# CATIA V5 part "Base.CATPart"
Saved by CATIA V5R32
Part number: Base
Bounding box of the stored display mesh (mm): x -23.876 to 23.876, y 0 to 88.9, z 0 to 54.102
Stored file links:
  D:\PROJECTS\Project 2022\CATIA V5 6R 2022\Resources\Part Files\c13_catia_v5_6r2022_prt\c13_catia_v5-6r2022_figr_13-45\Part & Asm files\Base.CATPart
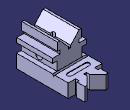
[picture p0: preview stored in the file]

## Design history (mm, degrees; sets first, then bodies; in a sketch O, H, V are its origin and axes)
Body1 (main body)
  Sketch1 on xy-plane, origin (0, 0, 0), H (1, 0, 0), V (0, 1, 0)
    line L1 (-23.876, 0) -> (23.876, 0)
    point P1 (-23.876, 0)
    point P2 (23.876, 0)
    construction line L2 (-23.876, 50.8) -> (23.876, 50.8)
    point P3 (-23.876, 50.8)
    point P4 (23.876, 50.8)
    line L3 (23.876, 0) -> (23.876, 72.898)
    point P5 (23.876, 72.898)
    line L4 (23.876, 72.898) -> (13.462, 72.898)
    point P6 (13.462, 72.898)
    line L5 (13.462, 72.898) -> (13.462, 77.724)
    point P7 (13.462, 77.724)
    line L6 (13.462, 77.724) -> (16.51, 77.724)
    point P8 (16.51, 77.724)
    line L7 (16.51, 77.724) -> (16.51, 88.9)
    point P9 (16.51, 88.9)
    line L8 (16.51, 88.9) -> (13.462, 88.9)
    point P10 (13.462, 88.9)
    line L9 (13.462, 88.9) -> (1.778, 77.724)
    point P11 (1.778, 77.724)
    line L10 (1.778, 77.724) -> (1.778, 72.898)
    point P12 (1.778, 72.898)
    line L11 (1.778, 72.898) -> (0, 72.898)
    point P13 (0, 72.898)
    point P14 (0, 72.898)
    point P15 (-1.778, 72.898)
    line L12 (-1.778, 72.898) -> (0, 72.898)
    point P16 (-1.778, 77.724)
    line L13 (-1.778, 77.724) -> (-1.778, 72.898)
    point P17 (-13.462, 88.9)
    line L14 (-13.462, 88.9) -> (-1.778, 77.724)
    point P18 (-16.51, 88.9)
    line L15 (-16.51, 88.9) -> (-13.462, 88.9)
    point P19 (-16.51, 77.724)
    line L16 (-16.51, 77.724) -> (-16.51, 88.9)
    point P20 (-13.462, 77.724)
    line L17 (-13.462, 77.724) -> (-16.51, 77.724)
    point P21 (-13.462, 72.898)
    line L18 (-13.462, 72.898) -> (-13.462, 77.724)
    point P22 (-23.876, 72.898)
    line L19 (-23.876, 72.898) -> (-13.462, 72.898)
    point P23 (-23.876, 50.8)
    point P24 (23.876, 50.8)
    construction line L20 (23.876, 50.8) -> (-23.876, 50.8)
    point P25 (-23.876, 0)
    line L21 (-23.876, 0) -> (-23.876, 72.898)
    length L1 = 47.752
    distance P2 V = 23.876
    distance L2 L1 = 50.8
    distance P5 L2 = 22.098
    distance L7 P1 = 40.386
    distance L5 P1 = 37.338
    distance L2 P7 = 26.924
    distance P9 L2 = 38.1
    distance P10 L3 = 10.414
    distance L10 L3 = 22.098
    distance L11 L2 = 22.098
    distance P11 L2 = 26.924
    horizontal: L1 H, L2 H, L4 H, L6 H, L8 H, L11 H
    coincidence: H L1, P13 V, P13 P14
    vertical: L3 V, L5 V, L7 V, L10 V
    symmetry: P13 P14 V, P12 P15 V, L11 L12 V, P11 P16 V, L10 L13 V, P10 P17 V, L9 L14 V, P9 P18 V, L8 L15 V, P8 P19 V, L7 L16 V, P7 P20 V, L6 L17 V, P6 P21 V, L5 L18 V, P5 P22 V, L4 L19 V, P4 P23 V, P3 P24 V, L2 L20 V, P2 P25 V, L3 L21 V
  Pad1: profile Sketch1, direction (0, 0, 1), length 19.05
  Sketch2 on face of Pad1, origin (23.876, 0, 0), H (0, 1, 0), V (0, 0, 1)
    point P1 (50.8, 19.05)
    line L1 (50.8, 19.05) -> (52.324, 16.4104)
    line L2 (52.324, 16.4104) -> (53.848, 19.05)
    line L3 (53.848, 19.05) -> (50.8, 19.05)
    reference projected line E1 (72.898, 19.05) -> (0, 19.05) from edge of Pad1
    length L2 = 3.048
    length L1 = 3.048
    distance P1 V = 50.8
    angle L1 L2 = 60
    horizontal: L3 H
    coincidence: L3 E1
  Pocket1: profile Sketch2, direction (-1, 0, 0), through (limit type 6)
  Sketch3 on face of Pad1, origin (0, 0, 0), H (1, 0, 0), V (0, 0, 1)
    line L1 (17.526, 19.05) -> (17.526, 31.75)
    point P1 (17.526, 19.05)
    point P2 (17.526, 31.75)
    line L2 (17.526, 31.75) -> (23.876, 31.75)
    point P3 (23.876, 31.75)
    line L3 (23.876, 31.75) -> (23.876, 38.1)
    point P4 (23.876, 38.1)
    line L4 (23.876, 38.1) -> (13.462, 38.1)
    point P5 (13.462, 38.1)
    line L5 (13.462, 38.1) -> (13.462, 42.926)
    point P6 (13.462, 42.926)
    line L6 (13.462, 42.926) -> (16.637, 42.926)
    point P7 (16.637, 42.926)
    line L7 (16.637, 42.926) -> (16.637, 54.102)
    point P8 (16.637, 54.102)
    reference projected line E1 (23.876, 19.05) -> (-23.876, 19.05) from edge of Pad1
    reference projected line E2 (23.876, 0) -> (23.876, 19.05) from edge of Pad1
    reference projected line E3 (-23.876, 19.05) -> (-23.876, 0) from edge of Pad1
    line L8 (16.637, 54.102) -> (13.462, 54.102)
    point P9 (13.462, 54.102)
    point P10 (1.651, 41.402)
    line L9 (1.651, 41.402) -> (1.651, 38.1)
    point P11 (1.651, 38.1)
    line L10 (1.651, 38.1) -> (0, 38.1)
    point P12 (0, 38.1)
    line L11 (1.651, 41.402) -> (13.462, 54.102)
    point P13 (-13.462, 54.102)
    point P14 (-1.651, 41.402)
    line L12 (-1.651, 41.402) -> (-13.462, 54.102)
    point P15 (0, 38.1)
    point P16 (-1.651, 38.1)
    line L13 (-1.651, 38.1) -> (0, 38.1)
    line L14 (-1.651, 41.402) -> (-1.651, 38.1)
    point P17 (-16.637, 54.102)
    line L15 (-16.637, 54.102) -> (-13.462, 54.102)
    point P18 (-16.637, 42.926)
    line L16 (-16.637, 42.926) -> (-16.637, 54.102)
    point P19 (-13.462, 42.926)
    line L17 (-13.462, 42.926) -> (-16.637, 42.926)
    point P20 (-13.462, 38.1)
    line L18 (-13.462, 38.1) -> (-13.462, 42.926)
    point P21 (-23.876, 38.1)
    line L19 (-23.876, 38.1) -> (-13.462, 38.1)
    point P22 (-23.876, 31.75)
    line L20 (-23.876, 31.75) -> (-23.876, 38.1)
    point P23 (-17.526, 31.75)
    line L21 (-17.526, 31.75) -> (-23.876, 31.75)
    point P24 (-17.526, 19.05)
    line L22 (-17.526, 19.05) -> (-17.526, 31.75)
    line L23 (-17.526, 19.05) -> (17.526, 19.05)
    distance V L1 = 17.526
    distance L2 H = 31.75
    distance L4 H = 38.1
    distance L6 H = 42.926
    distance L7 V = 16.637
    distance L5 E3 = 37.338
    distance V P9 = 13.462
    distance L8 H = 54.102
    distance L9 V = 1.651
    length L9 = 3.302
    vertical: L1 V, L3 V, L5 V, L7 V, L9 V
    horizontal: L2 H, L4 H, L6 H, L8 H, L10 H, L23 H
    coincidence: P1 E1, L3 E2, P11 L4, P12 V, P12 P15
    symmetry: P9 P13 V, P10 P14 V, L11 L12 V, P12 P15 V, P11 P16 V, L10 L13 V, L9 L14 V, P8 P17 V, L8 L15 V, P7 P18 V, L7 L16 V, P6 P19 V, L6 L17 V, P5 P20 V, L5 L18 V, P4 P21 V, L4 L19 V, P3 P22 V, L3 L20 V, P2 P23 V, L2 L21 V, P1 P24 V, L1 L22 V
  Pad2: profile Sketch3, direction (0, 1, 0), length 50.8
  Sketch4 on face of Pad1, origin (4.0235, 27.8102, 0), H (1, 0, 0), V (0, -1, 0)
    point P1 (-4.0235, 2.4102)
    reference projected line E1 (13.5025, -22.9898) -> (-21.5495, -22.9898) from edge of Pad2
    reference intersected line E2 through (-4.0235, 0) direction (0, 1) from yz-plane
    distance P1 E1 = 25.4
    coincidence: E2 P1
  Hole1: placed by Sketch4, at (0, 25.4, 0) direction (0, 0, 1), diameter 7.874, depth 54.102
  Sketch5 on face of Pad2, origin (17.526, 12.3932, 23.5222), H (0, 1, 0), V (0, 0, 1)
    point P1 (13.0068, 1.8778)
    reference projected line E1 (-12.3932, 8.2278) -> (-12.3932, -4.4722) from edge of Pad2
    reference projected line E2 (-12.3932, -23.5222) -> (60.5048, -23.5222) from edge of Pad1
    distance E1 P1 = 25.4
    distance E2 P1 = 25.4
  Hole2: placed by Sketch5, at (17.526, 25.4, 25.4) direction (-1, 0, 0), diameter 9.652, depth 54.102
  Sketch6 on face of Pad1, origin (0, 0, 19.05), H (1, 0, 0), V (0, 1, 0)
    construction line L1 (-23.876, 63.373) -> (23.876, 63.373)
    point P1 (-23.876, 63.373)
    point P2 (23.876, 63.373)
    reference projected line E1 (23.876, 53.848) -> (-23.876, 53.848) from edge of Pocket1
    construction line L2 (-12.7, 63.373) -> (12.7, 63.373)
    point P3 (-12.7, 63.373)
    line L3 (-12.7, 66.548) -> (12.7, 66.548)
    line L4 (12.7, 60.198) -> (-12.7, 60.198)
    arc A1 centre (12.7, 63.373) radius 3.175 from (12.7, 66.548) to (12.7, 60.198) cw
    arc A2 centre (-12.7, 63.373) radius 3.175 from (-12.7, 60.198) to (-12.7, 66.548) cw
    reference projected line E2 (23.876, 72.898) -> (23.876, 0) from edge of Pad1
    reference projected line E3 (-23.876, 72.898) -> (-23.876, 0) from edge of Pad1
    reference projected line E4 (-23.876, 72.898) -> (-23.876, 0) from edge of Pad1
    distance E1 L1 = 9.525
    radius A1 = 3.175
    distance A1 A2 = 31.75
    distance P3 E4 = 11.176
    horizontal: L1 H, L2 H
    coincidence: P3 L1, P2 E2, P1 E3
    tangency: A1 L3, A2 L3, A1 L4, A2 L4
    parallelism: L2 L3
  Pocket2: profile Sketch6, direction (0, 0, -1), length 0.762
